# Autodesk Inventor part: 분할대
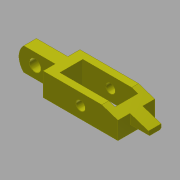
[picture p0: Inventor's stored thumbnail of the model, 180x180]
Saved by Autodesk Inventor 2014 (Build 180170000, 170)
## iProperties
Created: 2016-11
Part Number: 분할대
Material: 강철, 연강
Document SubType Name: Modeling
Designer: mduedu
Density: 1 g/cm^3
Appearance: Yellow
Author: mduedu
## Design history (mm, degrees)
sketch "스케치1"
  geometry: L1 (32.5, 16)-(-32.5, 16); L2 (-32.5, 16)-(-32.5, -16); L3 (-32.5, -16)-(32.5, -16); L4 (32.5, -16)-(32.5, 16); L5 (24, 10)-(-24, 10); L6 (-24, 10)-(-24, -10); L7 (-24, -10)-(24, -10); L8 (24, -10)-(24, 10); L9 (24, 0)-(-24, 0); L10 (0, -16)-(0, 16); 4 further points
  constraints: 20 end point, 7 midpoint, 4 parallel, 2 coincident, 2 horizontal, 2 perpendicular, 1 horizontal alignment
  dimensions: "d0" = 20 distance of L5.end L6.end; "d2" = 32 distance between parallel lines of L1 L3; "d3" = 48 distance of L5.start L5.end; "d4" = 65 distance of L1.start L1.end
extrude "돌출1" new body sketch "스케치1" distance "d5" = 20; taper "d6" = 0 deg
sketch "스케치2"
  geometry: L1 (0, 0)-(65, 0) reference; L2 (65, 0)-(65, 20) reference; L3 (0, 20)-(65, 20) reference; L4 (0, 0)-(0, 20) reference; L5 (32.5, 0)-(32.5, 20); C1 r 4 at (32.5, 10)
  constraints: 2 end point, 2 midpoint, 1 centre point
  dimensions: "d7" = 8 diameter of C1
extrude "돌출2" cut sketch "스케치2" stored distance "d8" = 20; taper "d9" = 0 deg
chamfer "모따기1" distance "d10" = 0.2; stored, may be unused: second distance "d11" = 2, angle "d12" = 45 deg
sketch "스케치3"
  geometry: L1 (-32.5, 0)-(-32.5, 20) reference; L2 (-32.5, 20)-(-59.798, 20); L3 (-64, 20)-(-64, 0); L4 (-64, 0)-(-59.798, 0); L5 (-32.5, 0)-(-32.5, 20); L6 (-59.798, 20)-(-64, 20); L7 (-59.798, 0)-(-32.5, 0); C1 r 4.2 at (0, 10) reference; C2 r 5 at (-50, 10); A1 r 14 centre (-50, 10) between (-59.798, 20) and (-59.798, 0); 1 further point
  constraints: 12 end point, 5 parallel, 2 centre point, 2 horizontal, 2 perpendicular, 2 point on circle, 1 coincident, 1 horizontal alignment, 1 tangent
  dimensions: "d13" = 64 distance from line of L3 C1.centre; "d14" = 14 radius of A1; "d15" = 10 diameter of C2
extrude "돌출3" join sketch "스케치3" stored distance "d16" = 11; taper "d17" = 0 deg
sketch "스케치4"
  geometry: L1 (32.5, 0)-(32.5, 20) reference; L2 (32.5, 20)-(48.5, 20); L3 (48.5, 20)-(48.5, 6); L4 (48.5, 6)-(32.5, 6); L5 (32.5, 6)-(32.5, 20); L6 (32.5, 0)-(-32.5, 0) reference; 1 further point
  constraints: 8 end point, 2 parallel, 1 horizontal, 1 perpendicular
  dimensions: "d18" = 16 distance of L1.end L2.end; "d19" = 6 distance between parallel lines of L4 L6
extrude "돌출4" join sketch "스케치4" stored distance "d20" = 11; taper "d21" = 0 deg
chamfer "모따기2" distance "d22" = 30; stored, may be unused: second distance "d23" = 10, angle "d24" = 45 deg
chamfer "모따기3" distance "d25" = 1; stored, may be unused: second distance "d26" = 10, angle "d27" = 45 deg
chamfer "모따기4" distance "d28" = 0.2; stored, may be unused: second distance "d29" = 10, angle "d30" = 45 deg
node "솔리드1"
node "투영된 루프1"
